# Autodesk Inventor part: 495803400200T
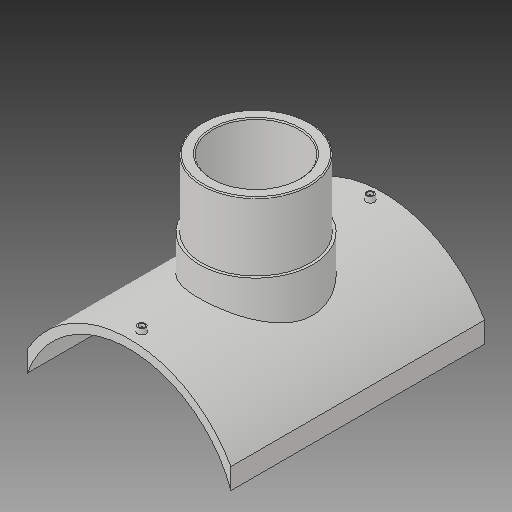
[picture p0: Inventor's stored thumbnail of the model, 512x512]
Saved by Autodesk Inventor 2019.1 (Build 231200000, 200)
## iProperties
Created: 2017-10
Part Number: 495803400200T
Material: Generic
Description: PLASSON BRANCH SADDLE  400x200
Document SubType Name: Modeling
Designer: KIM
Mass: 2754.05 g
Surface Area: 3037.44 cm^2
Volume: 2754.05 cm^3
Density: 1 g/cm^3
Appearance: Default
Author: KIM
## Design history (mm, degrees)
derived "495803.ipt"
feature "Solid1::495803.ipt"
tag "TaggingFeature1"
body "Solid1"
other parameters: "d1" = 16, "d2" = 377, "d4" = 0, "d12" = 225.6, "d13" = 14, "d14" = 211.5, "d16" = 5 deg, "d18" = 4, "d19" = 14, "d20" = 0, "d21" = 3, "d22" = 0, "d23" = 396, "d25" = 16, "d28" = 0, "d29" = 9.6, "d31" = 0, "d33" = 0, "d34" = 4, "d37" = 126, "d38" = 0, "d39" = 2, "B_" = 377, "x_" = 16, "D_" = 16
